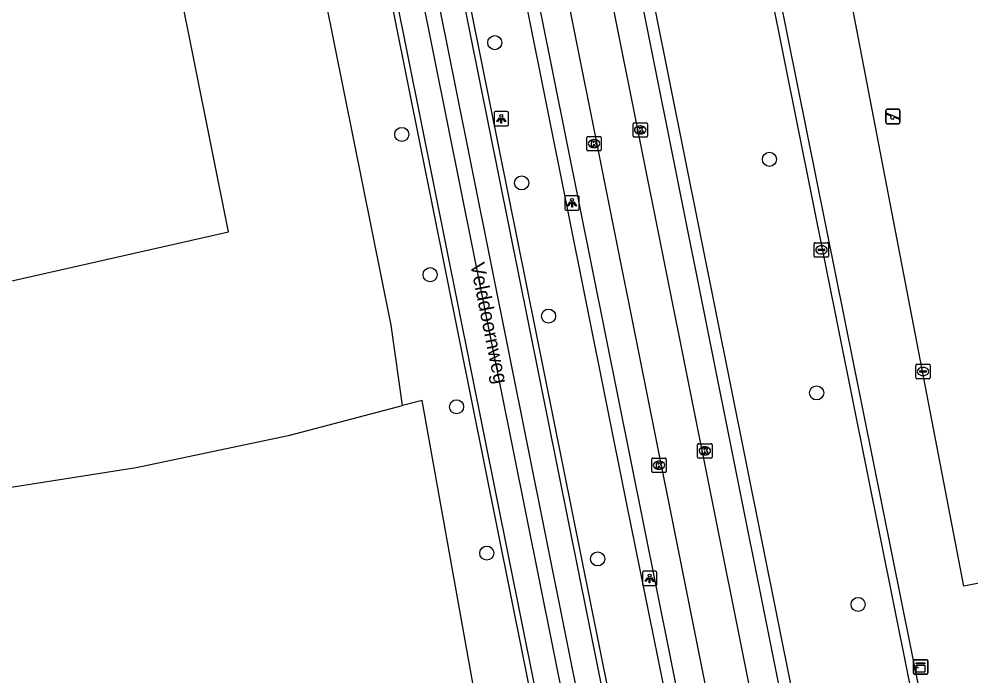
# Model space of a CAD drawing. Extents: x 160203 to 161526, y 379529 to 381797.
# Drawn here: x 160799.8 to 160865.9, y 380347.2 to 380392.8 of the extents above; entities that cross this region are included whole.
import ezdxf

# ---------------------------------------------------------------- set-up
doc = ezdxf.new("R2010")
doc.units = 0
for name, color, linetype in [('IMGEO_Boom', 7, 'Continuous'), ('IMGEO_Gemengd_bos', 7, 'Continuous'), ('IMGEO_Grasland_agrarisch', 7, 'Continuous'), ('IMGEO_Groenvoorziening', 7, 'Continuous'), ('IMGEO_Hek', 7, 'Continuous'), ('IMGEO_Kast', 7, 'Continuous'), ('IMGEO_Kolk', 7, 'Continuous'), ('IMGEO_Lichtpunt', 7, 'Continuous'), ('IMGEO_Loofbos', 7, 'Continuous'), ('IMGEO_Openbare_ruimte_label', 7, 'Continuous'), ('IMGEO_Rijbaan_lokaal_gesloten', 7, 'Continuous'), ('IMGEO_Rijbaan_lokaal_open', 7, 'Continuous'), ('IMGEO_Speelvoorziening', 7, 'Continuous'), ('IMGEO_Voetpad_open', 7, 'Continuous'), ('IMGEO_Waterleidingput', 7, 'Continuous')]:
    doc.layers.add(name, color=color, linetype=linetype)

msp = doc.modelspace()

# ---------------------------------------------------------------- linework, layer by layer
at = {"layer": 'IMGEO_Boom'}
for centre in [(160832.815, 380391.167), (160826.35, 380384.795), (160851.892, 380383.061), (160834.682, 380381.421), (160828.319, 380375.049), (160836.549, 380372.17), (160855.175, 380366.838), (160830.16, 380365.874), (160832.257, 380355.709), (160839.962, 380355.305), (160858.054, 380352.144)]:
    msp.add_circle(centre, 0.489, dxfattribs=at)
at = {"layer": 'IMGEO_Gemengd_bos'}
msp.add_lwpolyline([(160786.215, 380358.257), (160807.904, 380361.665), (160818.583, 380363.901), (160826.408, 380365.955)], dxfattribs=at)
at = {"layer": 'IMGEO_Grasland_agrarisch'}
msp.add_lwpolyline([(160775.372, 380369.231), (160814.313, 380378.028), (160810.816, 380395.452), (160792.299, 380392.893), (160790.929, 380411.368), (160771.323, 380410.232), (160770.881, 380415.989), (160759.176, 380415.089), (160754.769, 380413.373)], dxfattribs=at)
at = {"layer": 'IMGEO_Groenvoorziening'}
msp.add_lwpolyline([(160953.284, 380437.896), (160966.11, 380373.245), (160865.398, 380353.411), (160852.978, 380417.957), (160953.284, 380437.896)], dxfattribs=at)
at = {"layer": 'IMGEO_Hek'}
msp.add_lwpolyline([(160831.887, 380494.616), (160862.461, 380342.515)], dxfattribs=at)
at = {"layer": 'IMGEO_Kast'}
for p, q in [((160861.899, 380347.379), (160861.899, 380348.22)), ((160861.899, 380348.22), (160861.899, 380347.379)), ((160861.974, 380348.304), (160862.815, 380348.304)), ((160862.815, 380348.304), (160861.974, 380348.304)), ((160862.899, 380348.229), (160862.899, 380347.388)), ((160862.899, 380347.388), (160862.899, 380348.229)), ((160862.824, 380347.304), (160861.983, 380347.304)), ((160861.983, 380347.304), (160862.824, 380347.304))]:
    msp.add_line(p, q, dxfattribs=at)
for points in [[(160862.094, 380348.094), (160862.694, 380348.094), (160862.694, 380348.009), (160862.094, 380348.009), (160862.094, 380348.094)], [(160862.094, 380347.919), (160862.694, 380347.919), (160862.694, 380347.43), (160862.094, 380347.43), (160862.094, 380347.919)]]:
    msp.add_lwpolyline(points, dxfattribs=at)
msp.add_circle((160862.178, 380347.768), 0.0377, dxfattribs=at)
for centre, start, end in [((160861.977, 380348.226), 92.4484, 184.28452), ((160861.977, 380348.226), 92.4484, 184.28452), ((160862.821, 380348.226), 2.4484, 94.28452), ((160862.821, 380348.226), 2.4484, 94.28452), ((160861.977, 380347.382), 182.4484, 274.28452), ((160861.977, 380347.382), 182.4484, 274.28452), ((160862.821, 380347.382), 272.4484, 4.28452), ((160862.821, 380347.382), 272.4484, 4.28452)]:
    msp.add_arc(centre, 0.0779, start, end, dxfattribs=at)
at = {"layer": 'IMGEO_Kolk'}
for p, q in [((160842.418, 380384.677), (160842.418, 380385.529)), ((160842.493, 380385.603), (160843.345, 380385.603)), ((160842.906, 380385.383), (160842.931, 380385.383)), ((160843.419, 380385.529), (160843.419, 380384.677)), ((160839.211, 380383.729), (160839.211, 380384.581)), ((160839.286, 380384.655), (160840.138, 380384.655)), ((160839.699, 380384.435), (160839.724, 380384.435)), ((160840.212, 380384.581), (160840.212, 380383.729)), ((160843.345, 380384.603), (160842.493, 380384.603)), ((160842.929, 380384.823), (160842.904, 380384.823)), ((160840.138, 380383.655), (160839.286, 380383.655)), ((160839.722, 380383.875), (160839.697, 380383.875)), ((160846.907, 380362.385), (160846.907, 380363.237)), ((160846.982, 380363.311), (160847.834, 380363.311)), ((160847.908, 380363.237), (160847.908, 380362.385)), ((160847.418, 380362.531), (160847.393, 380362.531)), ((160847.395, 380363.091), (160847.42, 380363.091)), ((160843.725, 380361.389), (160843.725, 380362.241)), ((160843.8, 380362.315), (160844.652, 380362.315)), ((160844.213, 380362.095), (160844.238, 380362.095)), ((160844.726, 380362.241), (160844.726, 380361.389)), ((160847.834, 380362.311), (160846.982, 380362.311)), ((160844.652, 380361.315), (160843.8, 380361.315)), ((160844.236, 380361.535), (160844.211, 380361.535))]:
    msp.add_line(p, q, dxfattribs=at)
for points in [[(160842.418, 380384.677), (160842.418, 380385.529)], [(160842.493, 380385.603), (160843.345, 380385.603)], [(160842.739, 380385.303), (160842.862, 380385.303), (160842.862, 380385.152), (160842.992, 380385.303), (160843.156, 380385.303), (160843.01, 380385.152), (160843.163, 380384.903), (160843.011, 380384.903), (160842.926, 380385.067), (160842.862, 380385), (160842.862, 380384.903), (160842.739, 380384.903), (160842.739, 380385.303)], [(160843.419, 380385.529), (160843.419, 380384.677)], [(160839.211, 380383.729), (160839.211, 380384.581)], [(160839.286, 380384.655), (160840.138, 380384.655)], [(160839.532, 380384.355), (160839.655, 380384.355), (160839.655, 380384.204), (160839.785, 380384.355), (160839.949, 380384.355), (160839.803, 380384.204), (160839.956, 380383.955), (160839.804, 380383.955), (160839.719, 380384.119), (160839.655, 380384.052), (160839.655, 380383.955), (160839.532, 380383.955), (160839.532, 380384.355)], [(160840.212, 380384.581), (160840.212, 380383.729)], [(160843.345, 380384.603), (160842.493, 380384.603)], [(160840.138, 380383.655), (160839.286, 380383.655)], [(160846.907, 380362.385), (160846.907, 380363.237)], [(160846.982, 380363.311), (160847.834, 380363.311)], [(160847.908, 380363.237), (160847.908, 380362.385)], [(160847.228, 380363.011), (160847.351, 380363.011), (160847.351, 380362.86), (160847.481, 380363.011), (160847.645, 380363.011), (160847.499, 380362.86), (160847.652, 380362.611), (160847.5, 380362.611), (160847.415, 380362.775), (160847.351, 380362.708), (160847.351, 380362.611), (160847.228, 380362.611), (160847.228, 380363.011)], [(160843.725, 380361.389), (160843.725, 380362.241)], [(160843.8, 380362.315), (160844.652, 380362.315)], [(160844.046, 380362.015), (160844.169, 380362.015), (160844.169, 380361.864), (160844.299, 380362.015), (160844.463, 380362.015), (160844.317, 380361.864), (160844.47, 380361.615), (160844.318, 380361.615), (160844.233, 380361.779), (160844.169, 380361.712), (160844.169, 380361.615), (160844.046, 380361.615), (160844.046, 380362.015)], [(160844.726, 380362.241), (160844.726, 380361.389)], [(160847.834, 380362.311), (160846.982, 380362.311)], [(160844.652, 380361.315), (160843.8, 380361.315)]]:
    msp.add_lwpolyline(points, dxfattribs=at)
for centre, start, end in [((160842.495, 380385.527), 91.55205, 178.44795), ((160842.495, 380385.527), 91.55205, 178.44795), ((160843.343, 380385.527), 1.55205, 88.44795), ((160843.343, 380385.527), 1.55205, 88.44795), ((160839.288, 380384.579), 91.55205, 178.44795), ((160839.288, 380384.579), 91.55205, 178.44795), ((160840.136, 380384.579), 1.55205, 88.44795), ((160840.136, 380384.579), 1.55205, 88.44795), ((160842.495, 380384.679), 181.55205, 268.44795), ((160842.495, 380384.679), 181.55205, 268.44795), ((160843.343, 380384.679), 271.55205, 358.44795), ((160843.343, 380384.679), 271.55205, 358.44795), ((160839.288, 380383.731), 181.55205, 268.44795), ((160839.288, 380383.731), 181.55205, 268.44795), ((160840.136, 380383.731), 271.55205, 358.44795), ((160840.136, 380383.731), 271.55205, 358.44795), ((160846.984, 380363.235), 91.55205, 178.44795), ((160846.984, 380363.235), 91.55205, 178.44795), ((160847.832, 380363.235), 1.55205, 88.44795), ((160847.832, 380363.235), 1.55205, 88.44795), ((160843.802, 380362.239), 91.55205, 178.44795), ((160843.802, 380362.239), 91.55205, 178.44795), ((160844.65, 380362.239), 1.55205, 88.44795), ((160844.65, 380362.239), 1.55205, 88.44795), ((160846.984, 380362.387), 181.55205, 268.44795), ((160846.984, 380362.387), 181.55205, 268.44795), ((160847.832, 380362.387), 271.55205, 358.44795), ((160847.832, 380362.387), 271.55205, 358.44795), ((160843.802, 380361.391), 181.55205, 268.44795), ((160843.802, 380361.391), 181.55205, 268.44795), ((160844.65, 380361.391), 271.55205, 358.44795), ((160844.65, 380361.391), 271.55205, 358.44795)]:
    msp.add_arc(centre, 0.0765, start, end, dxfattribs=at)
for centre, major_axis, ratio, start_param, end_param in [((160842.905, 380385.103), (-0.387, 0.002), 0.722429, 4.712389, 7.853982), ((160842.93, 380385.103), (-0.39, 0.002), 0.717154, 1.570796, 4.712389), ((160839.698, 380384.155), (-0.387, 0.002), 0.722429, 4.712389, 7.853982), ((160839.723, 380384.155), (-0.39, 0.002), 0.717154, 1.570796, 4.712389), ((160847.394, 380362.811), (-0.387, 0.002), 0.722429, 4.712389, 7.853982), ((160847.419, 380362.811), (-0.39, 0.002), 0.717154, 1.570796, 4.712389), ((160844.212, 380361.815), (-0.387, 0.002), 0.722429, 4.712389, 7.853982), ((160844.237, 380361.815), (-0.39, 0.002), 0.717154, 1.570796, 4.712389)]:
    msp.add_ellipse(centre, major_axis=major_axis, ratio=ratio, start_param=start_param, end_param=end_param, dxfattribs=at)
at = {"layer": 'IMGEO_Lichtpunt'}
for p, q in [((160833.669, 380386.381), (160832.861, 380386.381)), ((160833.669, 380386.381), (160832.861, 380386.381)), ((160832.767, 380386.286), (160832.767, 380385.479)), ((160832.767, 380386.286), (160832.767, 380385.479)), ((160833.763, 380385.479), (160833.763, 380386.286)), ((160833.763, 380385.479), (160833.763, 380386.286)), ((160832.861, 380385.385), (160833.669, 380385.385)), ((160832.861, 380385.385), (160833.669, 380385.385)), ((160837.683, 380380.441), (160837.683, 380379.634)), ((160837.683, 380380.441), (160837.683, 380379.634)), ((160838.585, 380380.536), (160837.777, 380380.536)), ((160838.585, 380380.536), (160837.777, 380380.536)), ((160838.679, 380379.634), (160838.679, 380380.441)), ((160838.679, 380379.634), (160838.679, 380380.441)), ((160837.777, 380379.54), (160838.585, 380379.54)), ((160837.777, 380379.54), (160838.585, 380379.54)), ((160843.069, 380354.353), (160843.069, 380353.546)), ((160843.069, 380354.353), (160843.069, 380353.546)), ((160843.971, 380354.448), (160843.163, 380354.448)), ((160843.971, 380354.448), (160843.163, 380354.448)), ((160844.065, 380353.546), (160844.065, 380354.353)), ((160844.065, 380353.546), (160844.065, 380354.353)), ((160843.163, 380353.452), (160843.971, 380353.452)), ((160843.163, 380353.452), (160843.971, 380353.452))]:
    msp.add_line(p, q, dxfattribs=at)
for points in [[(160833.141, 380385.95), (160833.18, 380385.922), (160832.992, 380385.66), (160832.954, 380385.687), (160833.141, 380385.95)], [(160833.243, 380385.902), (160833.29, 380385.902), (160833.29, 380385.58), (160833.243, 380385.58), (160833.243, 380385.902)], [(160833.353, 380385.922), (160833.391, 380385.949), (160833.578, 380385.687), (160833.539, 380385.659), (160833.353, 380385.922)], [(160838.057, 380380.105), (160838.096, 380380.077), (160837.908, 380379.815), (160837.87, 380379.842), (160838.057, 380380.105)], [(160838.159, 380380.057), (160838.206, 380380.057), (160838.206, 380379.735), (160838.159, 380379.735), (160838.159, 380380.057)], [(160838.269, 380380.077), (160838.307, 380380.104), (160838.494, 380379.842), (160838.455, 380379.814), (160838.269, 380380.077)], [(160843.443, 380354.017), (160843.482, 380353.989), (160843.294, 380353.727), (160843.256, 380353.754), (160843.443, 380354.017)], [(160843.545, 380353.969), (160843.592, 380353.969), (160843.592, 380353.647), (160843.545, 380353.647), (160843.545, 380353.969)], [(160843.655, 380353.989), (160843.693, 380354.016), (160843.88, 380353.754), (160843.841, 380353.726), (160843.655, 380353.989)]]:
    msp.add_lwpolyline(points, dxfattribs=at)
for centre in [(160833.266, 380386.084), (160838.182, 380380.239), (160843.568, 380354.151)]:
    msp.add_circle(centre, 0.0994, dxfattribs=at)
for centre, start, end in [((160832.861, 380386.286), 90, 180), ((160832.861, 380386.286), 90, 180), ((160833.669, 380386.286), 0, 90), ((160833.669, 380386.286), 0, 90), ((160832.861, 380385.479), 180, 270), ((160832.861, 380385.479), 180, 270), ((160833.669, 380385.479), 270, 0), ((160833.669, 380385.479), 270, 360), ((160837.777, 380380.441), 90, 180), ((160837.777, 380380.441), 90, 180), ((160838.585, 380380.441), 0, 90), ((160838.585, 380380.441), 0, 90), ((160837.777, 380379.634), 180, 270), ((160837.777, 380379.634), 180, 270), ((160838.585, 380379.634), 270, 0), ((160838.585, 380379.634), 270, 360), ((160843.163, 380354.353), 90, 180), ((160843.163, 380354.353), 90, 180), ((160843.971, 380354.353), 0, 90), ((160843.971, 380354.353), 0, 90), ((160843.163, 380353.546), 180, 270), ((160843.163, 380353.546), 180, 270), ((160843.971, 380353.546), 270, 0), ((160843.971, 380353.546), 270, 360)]:
    msp.add_arc(centre, 0.0946, start, end, dxfattribs=at)
at = {"layer": 'IMGEO_Loofbos'}
for points in [[(160863.045, 380342.63), (160833.499, 380489.33), (160833.56, 380489.783), (160833.852, 380490.316), (160834.2, 380490.611), (160834.638, 380490.788), (160879.901, 380499.518), (160902.101, 380503.8), (160944.615, 380512.001), (160946.869, 380502.452)], [(160831.887, 380494.616), (160862.461, 380342.515)], [(160826.408, 380365.955), (160825.615, 380371.544), (160820.389, 380397.556), (160816.06, 380419.106), (160814.776, 380425.496), (160813.712, 380431.457), (160802.128, 380489.092), (160796.963, 380489.418)], [(160839.859, 380298.895), (160827.774, 380366.314), (160826.408, 380365.955)]]:
    msp.add_lwpolyline(points, dxfattribs=at)
at = {"layer": 'IMGEO_Rijbaan_lokaal_gesloten'}
for points in [[(160814.424, 380511.244), (160818.287, 380491.97), (160848.829, 380339.603)], [(160851.769, 380340.218), (160821.234, 380492.423), (160817.512, 380510.978)], [(160807.391, 380496.064), (160807.806, 380496.157), (160808.357, 380496.254), (160809.488, 380490.62), (160847.878, 380299.47), (160857.878, 380249.092), (160856.862, 380248.916)], [(160856.862, 380248.916), (160846.915, 380299.112), (160808.457, 380490.462), (160808.139, 380492.044), (160807.391, 380496.064)], [(160841.352, 380340.899), (160811.161, 380490.877), (160810.731, 380493.012), (160810.646, 380493.434)], [(160806.108, 380492.099), (160806.281, 380492.144), (160806.674, 380490.188), (160845.136, 380298.897), (160858.94, 380229.148), (160865.008, 380198.49)]]:
    msp.add_lwpolyline(points, dxfattribs=at)
at = {"layer": 'IMGEO_Rijbaan_lokaal_open'}
for points in [[(160841.352, 380340.899), (160841.726, 380341.019), (160841.379, 380342.789), (160814.089, 380478.303), (160811.026, 380493.513)], [(160806.108, 380492.099), (160805.945, 380492.03), (160806.217, 380490.57), (160844.613, 380299.608), (160849.881, 380272.972)]]:
    msp.add_lwpolyline(points, dxfattribs=at)
at = {"layer": 'IMGEO_Speelvoorziening'}
for p, q in [((160859.973, 380385.638), (160859.973, 380386.438)), ((160859.973, 380386.438), (160859.973, 380385.638)), ((160860.073, 380386.538), (160860.863, 380386.538)), ((160860.863, 380386.538), (160860.073, 380386.538)), ((160860.963, 380386.438), (160860.963, 380385.638)), ((160860.963, 380385.638), (160860.963, 380386.438)), ((160860.356, 380386.066), (160860.017, 380386.203)), ((160860.042, 380386.263), (160860.918, 380385.91)), ((160860.894, 380385.85), (160860.554, 380385.987)), ((160860.863, 380385.538), (160860.073, 380385.538)), ((160860.073, 380385.538), (160860.863, 380385.538))]:
    msp.add_line(p, q, dxfattribs=at)
for centre, radius, start, end in [((160860.073, 380386.438), 0.1, 90, 180), ((160860.073, 380386.438), 0.1, 90, 180), ((160860.863, 380386.438), 0.1, 0, 90), ((160860.863, 380386.438), 0.1, 360, 90), ((160860.073, 380385.638), 0.1, 180, 270), ((160860.073, 380385.638), 0.1, 180, 270), ((160860.03, 380386.233), 0.0327, 68.07798, 248.07798), ((160860.435, 380385.976), 0.12, 130.99278, 5.16318), ((160860.863, 380385.638), 0.1, 270, 0), ((160860.863, 380385.638), 0.1, 270, 0), ((160860.906, 380385.88), 0.0327, 248.07798, 68.07798)]:
    msp.add_arc(centre, radius, start, end, dxfattribs=at)
at = {"layer": 'IMGEO_Voetpad_open'}
for points in [[(160819.469, 380511.448), (160823.223, 380492.728), (160853.643, 380341.04)], [(160846.061, 380339.046), (160841.959, 380359.232), (160830.916, 380414.289), (160819.918, 380469.339), (160814.915, 380494.379)], [(160846.771, 380339.726), (160816.238, 380491.656), (160815.85, 380493.584), (160815.874, 380493.74)], [(160854.574, 380340.734), (160839.604, 380415.212), (160824.092, 380492.861)]]:
    msp.add_lwpolyline(points, dxfattribs=at)
at = {"layer": 'IMGEO_Waterleidingput'}
for p, q in [((160855.008, 380376.347), (160855.008, 380377.199)), ((160855.083, 380377.273), (160855.935, 380377.273)), ((160855.496, 380377.053), (160855.521, 380377.053)), ((160856.009, 380377.199), (160856.009, 380376.347)), ((160855.267, 380376.767), (160855.267, 380376.779)), ((160855.705, 380376.73), (160855.307, 380376.73)), ((160855.31, 380376.816), (160855.708, 380376.816)), ((160855.519, 380376.493), (160855.494, 380376.493)), ((160855.751, 380376.779), (160855.751, 380376.767)), ((160855.935, 380376.273), (160855.083, 380376.273)), ((160862.066, 380367.9), (160862.066, 380368.752)), ((160862.141, 380368.826), (160862.993, 380368.826)), ((160862.554, 380368.606), (160862.579, 380368.606)), ((160863.067, 380368.752), (160863.067, 380367.9)), ((160862.993, 380367.826), (160862.141, 380367.826)), ((160862.325, 380368.32), (160862.325, 380368.332)), ((160862.763, 380368.283), (160862.365, 380368.283)), ((160862.368, 380368.369), (160862.766, 380368.369)), ((160862.577, 380368.046), (160862.552, 380368.046)), ((160862.809, 380368.332), (160862.809, 380368.32))]:
    msp.add_line(p, q, dxfattribs=at)
for points in [[(160855.008, 380376.347), (160855.008, 380377.199)], [(160855.083, 380377.273), (160855.935, 380377.273)], [(160856.009, 380377.199), (160856.009, 380376.347)], [(160855.935, 380376.273), (160855.083, 380376.273)], [(160862.066, 380367.9), (160862.066, 380368.752)], [(160862.141, 380368.826), (160862.993, 380368.826)], [(160863.067, 380368.752), (160863.067, 380367.9)], [(160862.993, 380367.826), (160862.141, 380367.826)]]:
    msp.add_lwpolyline(points, dxfattribs=at)
for centre, radius, start, end in [((160855.085, 380377.197), 0.0765, 91.55205, 178.44795), ((160855.085, 380377.197), 0.0765, 91.55205, 178.44795), ((160855.933, 380377.197), 0.0765, 1.55205, 88.44795), ((160855.933, 380377.197), 0.0765, 1.55205, 88.44795), ((160855.307, 380376.776), 0.0403, 85.87752, 175.75265), ((160855.304, 380376.766), 0.0366, 178.93798, 274.71019), ((160855.708, 380376.773), 0.043, 264.86636, 352.45326), ((160855.712, 380376.778), 0.0386, 1.73085, 96.63898), ((160855.085, 380376.349), 0.0765, 181.55205, 268.44795), ((160855.085, 380376.349), 0.0765, 181.55205, 268.44795), ((160855.933, 380376.349), 0.0765, 271.55205, 358.44795), ((160855.933, 380376.349), 0.0765, 271.55205, 358.44795), ((160862.143, 380368.75), 0.0765, 91.55205, 178.44795), ((160862.143, 380368.75), 0.0765, 91.55205, 178.44795), ((160862.991, 380368.75), 0.0765, 1.55205, 88.44795), ((160862.991, 380368.75), 0.0765, 1.55205, 88.44795), ((160862.143, 380367.902), 0.0765, 181.55205, 268.44795), ((160862.143, 380367.902), 0.0765, 181.55205, 268.44795), ((160862.365, 380368.329), 0.0403, 85.87752, 175.75265), ((160862.362, 380368.319), 0.0366, 178.93798, 274.71019), ((160862.766, 380368.326), 0.043, 264.86636, 352.45326), ((160862.77, 380368.331), 0.0386, 1.73085, 96.63898), ((160862.991, 380367.902), 0.0765, 271.55205, 358.44795), ((160862.991, 380367.902), 0.0765, 271.55205, 358.44795)]:
    msp.add_arc(centre, radius, start, end, dxfattribs=at)
for centre, major_axis, ratio, start_param, end_param in [((160855.495, 380376.773), (-0.387, 0.002), 0.722429, 4.712389, 7.853982), ((160855.52, 380376.773), (-0.39, 0.002), 0.717154, 1.570796, 4.712389), ((160862.553, 380368.326), (-0.387, 0.002), 0.722429, 4.712389, 7.853982), ((160862.578, 380368.326), (-0.39, 0.002), 0.717154, 1.570796, 4.712389)]:
    msp.add_ellipse(centre, major_axis=major_axis, ratio=ratio, start_param=start_param, end_param=end_param, dxfattribs=at)

# ---------------------------------------------------------------- texts
at = {"layer": 'IMGEO_Openbare_ruimte_label'}
msp.add_text('Velddoornweg', height=1, rotation=281.36614, dxfattribs=at).set_placement((160831.104, 380375.785))

doc.saveas('drawing.dxf')
